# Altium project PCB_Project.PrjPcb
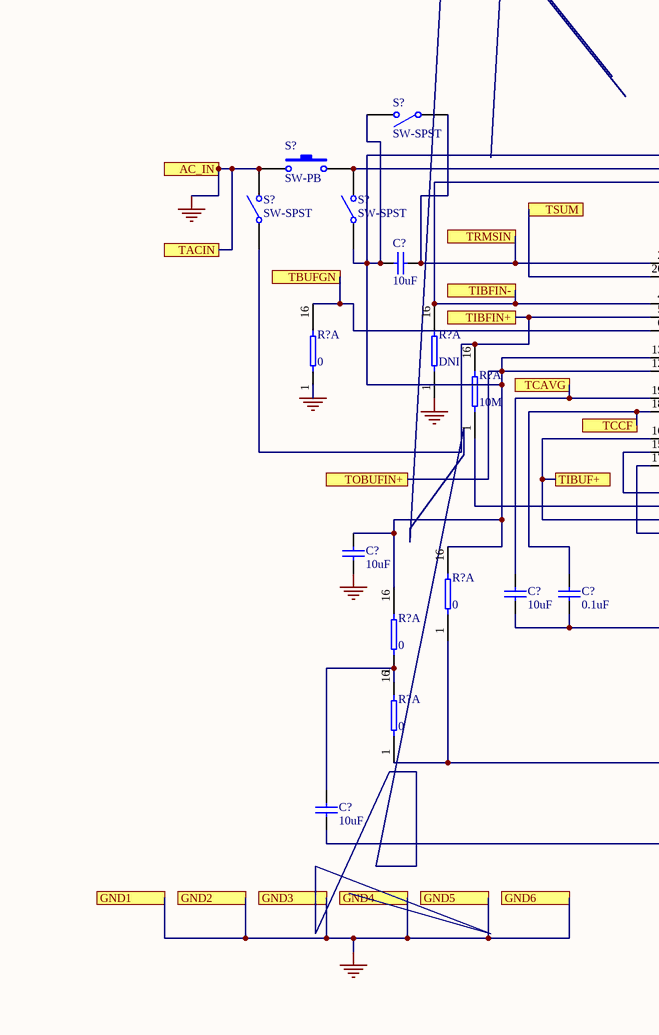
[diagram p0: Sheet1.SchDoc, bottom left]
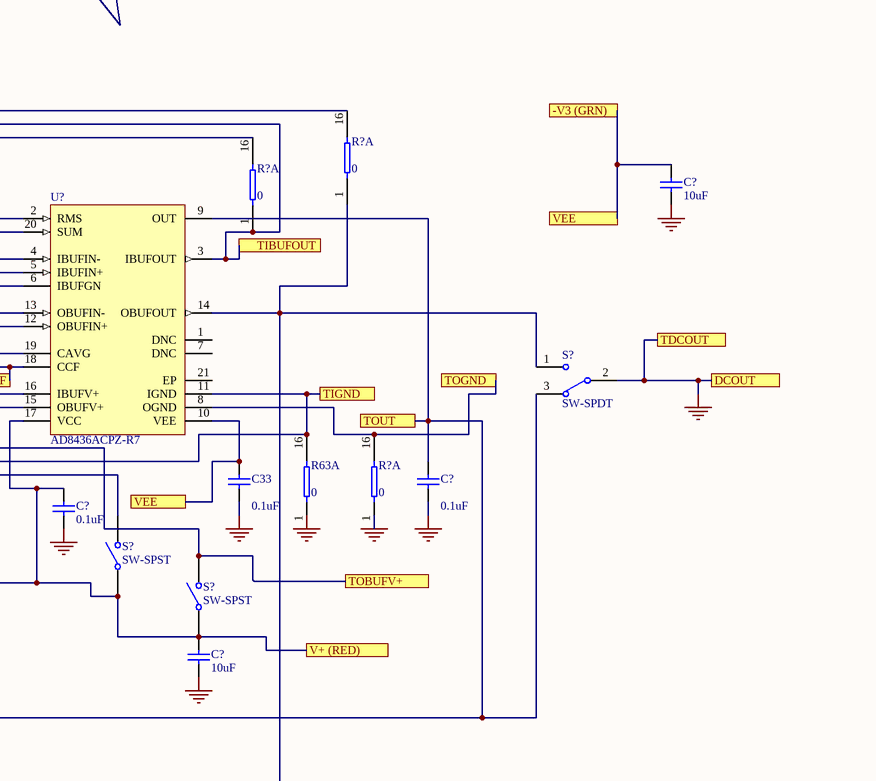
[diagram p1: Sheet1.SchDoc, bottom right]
1 sheet, 28 parts. Net scope: flat (ports and power ports of the same name join across sheets).

## Sheet Sheet1.SchDoc
size A4

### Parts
(Parts that share a designator on the sheet are numbered #1, #2 ... from top to bottom, then left to right.)
C33  value 0.1uF  [RAD-0.3]  (hidden comment: Cap)
C?#1  value 10uF  [RAD-0.3]  (hidden comment: Cap)
C?#2  value 10uF  [RAD-0.3]  (hidden comment: Cap)
C?#3  value 0.1uF  [RAD-0.3]  (hidden comment: Cap)
C?#4  value 10uF  [RAD-0.3]  (hidden comment: Cap)
C?#5  value 0.1uF  [RAD-0.3]  (hidden comment: Cap)
C?#6  value 10uF  [RAD-0.3]  (hidden comment: Cap)
C?#7  value 0.1uF  [RAD-0.3]  (hidden comment: Cap)
C?#8  value 10uF  [RAD-0.3]  (hidden comment: Cap)
C?#9  value 10uF  [RAD-0.3]  (hidden comment: Cap)
R63  value 0  [DIP-16]  (hidden comment: Res Pack2)  (part A of 8)
R?#1  value 0  [DIP-16]  (hidden comment: Res Pack2)  (part A of 8)
R?#2  value 0  [DIP-16]  (hidden comment: Res Pack2)  (part A of 8)
R?#3  value 0  [DIP-16]  (hidden comment: Res Pack2)  (part A of 8)
R?#4  value DNI  [DIP-16]  (hidden comment: Res Pack2)  (part A of 8)
R?#5  value 10M  [DIP-16]  (hidden comment: Res Pack2)  (part A of 8)
R?#6  value 0  [DIP-16]  (hidden comment: Res Pack2)  (part A of 8)
R?#7  value 0  [DIP-16]  (hidden comment: Res Pack2)  (part A of 8)
R?#8  value 0  [DIP-16]  (hidden comment: Res Pack2)  (part A of 8)
R?#9  value 0  [DIP-16]  (hidden comment: Res Pack2)  (part A of 8)
S?#1  SW-SPST  [SPST-2]
S?#2  SW-PB  [SPST-2]
S?#3  SW-SPST  [SPST-2]
S?#4  SW-SPST  [SPST-2]
S?#5  SW-SPDT  [TL36WW15050]
S?#6  SW-SPST  [SPST-2]
S?#7  SW-SPST  [SPST-2]
U?  AD8436ACPZ-R7  [ADI-CP-20-10_M]

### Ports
-V3 (GRN), AC_IN, DCOUT, GND1, GND2, GND3, GND4, GND5, GND6, TACIN, TBUFGN, TCAVG, TCCF, TDCOUT, TIBFIN+, TIBFIN-, TIBUF+, TIBUFOUT, TIGND, TOBUFIN+, TOBUFV+, TOGND, TOUT, TRMSIN, TSUM, V+ (RED), VEE

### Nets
GND: C33.2 C?#1.1 C?#3.2 C?#4.1 C?#5.1 C?#8.1 R?#3.1 R?#4.1 R?#6.1 S?#2.1 S?#3.2(NO) S?#5.2 ; port AC_IN, port TACIN, port TDCOUT, port DCOUT, port GND1, port GND2, port GND3, port GND4, port GND5, port GND6
NetC33_1: C33.1 C?#1.2 U?.10(VEE) ; port VEE, port -V3 (GRN)
NetC?#2_1: C?#2.1 C?#4.2 R?#1.16 R?#7.16 R?#8.16 S?#1.2(NO) S?#4.1(COMMON) U?.12(OBUFIN+) U?.13(OBUFIN-) ; port TOBUFIN+
NetC?#2_2: C?#2.2 S?#1.1(COMMON) U?.2(RMS) ; port TRMSIN
NetC?#3_1: C?#3.1 R?#7.1 R?#9.1 S?#5.3 U?.9(OUT) ; port TOUT
NetC?#5_2: C?#5.2 C?#6.1 C?#7.1 C?#8.2 S?#6.1(COMMON) S?#7.1(COMMON) U?.17(VCC) ; port V+ (RED)
NetC?#6_2: C?#6.2 U?.19(CAVG) ; port TCAVG
NetC?#7_2: C?#7.2 U?.18(CCF) ; port TCCF
NetC?#9_1: C?#9.1 R?#1.1 S?#5.1 U?.14(OBUFOUT)
NetC?#9_2: C?#9.2 R?#8.1 R?#9.16
NetR63_16: R63.16 R?#5.1 U?.11(IGND) ; port TIGND
NetR?#2_1: R?#2.1 S?#2.2 S?#4.2(NO) U?.3(IBUFOUT) ; port TIBUFOUT
NetR?#2_16: R?#2.16 R?#4.16 U?.4(IBUFIN-) ; port TIBFIN-
NetR?#3_16: R?#3.16 U?.6(IBUFGN) ; port TBUFGN
NetR?#5_16: R?#5.16 S?#3.1(COMMON) U?.5(IBUFIN+) ; port TIBFIN+
NetR?#6_16: R?#6.16 U?.8(OGND) ; port TOGND
NetS?#6_2: S?#6.2(NO) U?.16(IBUFV+) ; port TIBUF+
NetS?#7_2: S?#7.2(NO) U?.15(OBUFV+) ; port TOBUFV+
NetU?_20: U?.20(SUM) ; port TSUM

Not connected (* = marked no-connect by the designer): R63 1; U? 1(DNC) 7(DNC) 21(EP)

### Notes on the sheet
- Labels drawn without touching a wire or pin: GND

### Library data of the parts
C33 C?#1-C?#9 = Cap: Capacitor
R63 R?#1-R?#9 = Res Pack2: Isolated Resistor Network - Parts; Sim Note: Enter the Resistance value into parameter field.
S?#1 S?#3 S?#4 S?#6 S?#7 = SW-SPST: Single-Pole, Single-Throw Switch
S?#2 = SW-PB: Switch
S?#5 = SW-SPDT: SPDT Subminiature Toggle Switch, Right Angle Mounting, Vertical Actuation
U? = CMP-0527-00003-3: Low Cost, Low Power, True RMS-to-DC Converter, 4.8 to 36 V Single Supply, -40 to 125 degC, 20-Pin QFN (CP-20-10); Manufacturer: Analog Devices; -3dB Bandwidth: 950 KHz; Max Vin (V-rms): 3 V rms; V Span (min): 4.8 V; Supply Current: 300 uA; V Span (max): 36 V; Error (%@ CF: 3)=0.5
